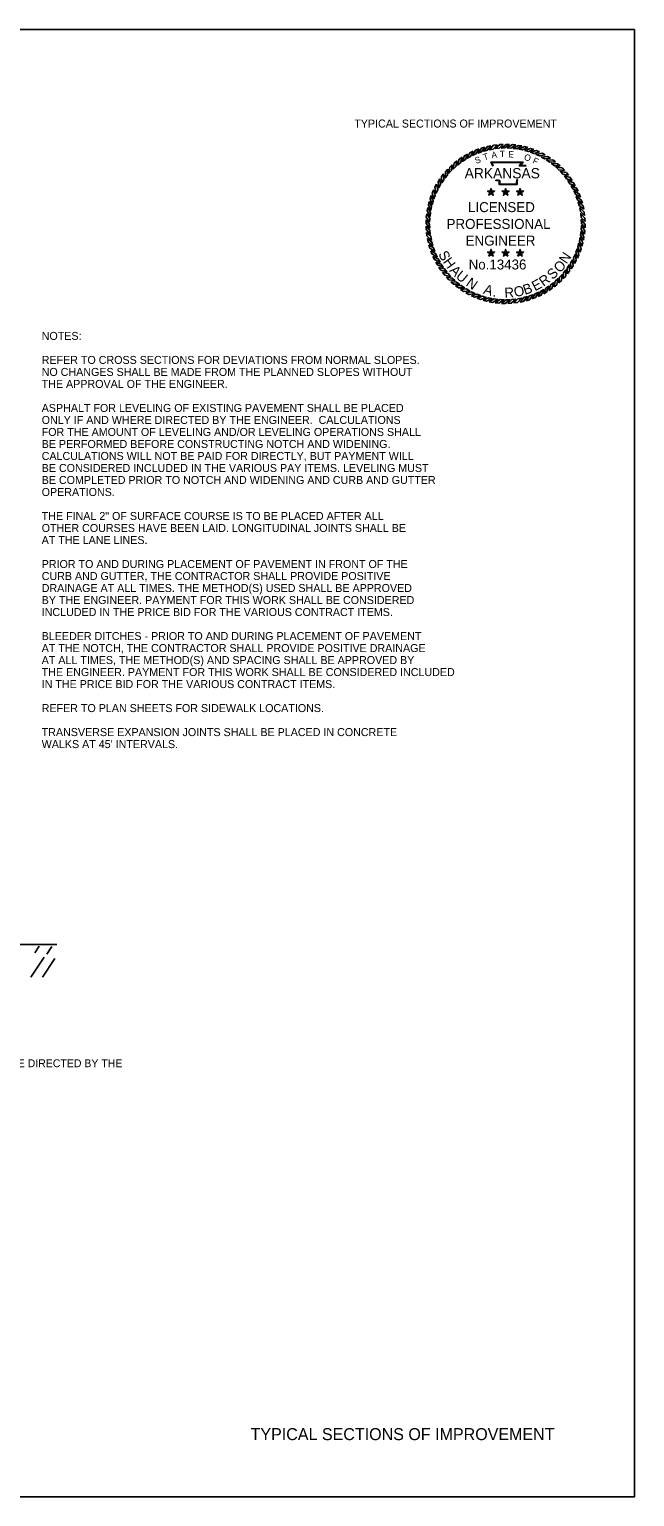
# Model space of a CAD drawing. Extents: x 1001270 to 1003428, y 1840152 to 1842912.
# Drawn here: x 1001928.1 to 1001973.5, y 1840287.7 to 1840397.7 of the extents above; entities that cross this region are included whole.
import ezdxf

# ---------------------------------------------------------------- set-up
doc = ezdxf.new("R2010")
doc.units = 0
for name, color, linetype in [('1', 7, 'Continuous'), ('19', 7, 'Continuous'), ('60', 7, 'Continuous'), ('Default', 7, 'Continuous'), ('G-ANNO-SYMB', 7, 'Continuous')]:
    doc.layers.add(name, color=color, linetype=linetype)

msp = doc.modelspace()

# ---------------------------------------------------------------- linework, layer by layer
at = {"layer": '1'}
msp.add_lwpolyline([(1001973.51, 1840397.72), (1001803.51, 1840397.72), (1001803.51, 1840287.72), (1001973.51, 1840287.72)], close=True, dxfattribs=at)
msp.add_lwpolyline([(1001973.51, 1840397.72), (1001803.51, 1840397.72), (1001803.51, 1840287.72), (1001973.51, 1840287.72)], close=True, dxfattribs=at)
at = {"layer": '19'}
for p, q in [((1001928.51, 1840328.49), (1001928.84, 1840328.98)), ((1001929.41, 1840328.4), (1001929.79, 1840328.97)), ((1001928.22, 1840326.68), (1001929.22, 1840328.16)), ((1001929.08, 1840326.68), (1001930.02, 1840328.06))]:
    msp.add_line(p, q, dxfattribs=at)
msp.add_lwpolyline([(1001877.51, 1840330.24), (1001892.2, 1840330.41), (1001903.17, 1840330.16), (1001908.95, 1840329.52), (1001918.56, 1840329.12), (1001930.17, 1840329.12)], dxfattribs=at)
at = {"layer": 'G-ANNO-SYMB'}
for points in [[(1001963.66, 1840389.1), (1001963.4, 1840389.09), (1001963.06, 1840388.78), (1001963.34, 1840388.81)], [(1001964.12, 1840389.1), (1001963.87, 1840389.1), (1001963.51, 1840388.82), (1001963.78, 1840388.83)], [(1001960.57, 1840388.13), (1001960.35, 1840387.99), (1001960.23, 1840387.55), (1001960.45, 1840387.72)], [(1001960.97, 1840388.37), (1001960.74, 1840388.25), (1001960.58, 1840387.82), (1001960.82, 1840387.97)], [(1001961.39, 1840388.58), (1001961.16, 1840388.47), (1001960.96, 1840388.06), (1001961.2, 1840388.19)], [(1001961.82, 1840388.76), (1001961.58, 1840388.67), (1001961.36, 1840388.27), (1001961.61, 1840388.38)], [(1001962.27, 1840388.9), (1001962.02, 1840388.82), (1001961.77, 1840388.45), (1001962.03, 1840388.54)], [(1001962.73, 1840389), (1001962.47, 1840388.95), (1001962.19, 1840388.59), (1001962.46, 1840388.66)], [(1001963.19, 1840389.07), (1001962.93, 1840389.04), (1001962.62, 1840388.7), (1001962.89, 1840388.75)], [(1001964.59, 1840389.06), (1001964.34, 1840389.08), (1001963.95, 1840388.83), (1001964.23, 1840388.82)], [(1001965.05, 1840388.98), (1001964.8, 1840389.02), (1001964.4, 1840388.8), (1001964.68, 1840388.77)], [(1001965.51, 1840388.86), (1001965.26, 1840388.93), (1001964.84, 1840388.74), (1001965.11, 1840388.68)], [(1001965.95, 1840388.71), (1001965.71, 1840388.8), (1001965.28, 1840388.64), (1001965.55, 1840388.57)], [(1001966.38, 1840388.53), (1001966.15, 1840388.63), (1001965.71, 1840388.51), (1001965.97, 1840388.41)], [(1001966.8, 1840388.31), (1001966.57, 1840388.44), (1001966.12, 1840388.35), (1001966.37, 1840388.23)], [(1001967.19, 1840388.06), (1001966.98, 1840388.2), (1001966.52, 1840388.15), (1001966.77, 1840388.01)], [(1001959.49, 1840387.23), (1001959.32, 1840387.04), (1001959.3, 1840386.59), (1001959.47, 1840386.8)], [(1001959.82, 1840387.56), (1001959.64, 1840387.39), (1001959.58, 1840386.93), (1001959.77, 1840387.13)], [(1001960.18, 1840387.86), (1001959.98, 1840387.7), (1001959.89, 1840387.25), (1001960.1, 1840387.44)], [(1001967.57, 1840387.78), (1001967.37, 1840387.94), (1001966.91, 1840387.92), (1001967.14, 1840387.77)], [(1001967.92, 1840387.48), (1001967.73, 1840387.65), (1001967.28, 1840387.67), (1001967.49, 1840387.49)], [(1001968.25, 1840387.14), (1001968.07, 1840387.33), (1001967.62, 1840387.38), (1001967.82, 1840387.19)], [(1001968.55, 1840386.78), (1001968.39, 1840386.98), (1001967.94, 1840387.07), (1001968.13, 1840386.87)], [(1001958.65, 1840386.11), (1001958.53, 1840385.88), (1001958.62, 1840385.43), (1001958.74, 1840385.69)], [(1001958.9, 1840386.51), (1001958.76, 1840386.29), (1001958.81, 1840385.84), (1001958.95, 1840386.08)], [(1001959.18, 1840386.88), (1001959.02, 1840386.68), (1001959.04, 1840386.22), (1001959.2, 1840386.45)], [(1001968.82, 1840386.4), (1001968.68, 1840386.61), (1001968.24, 1840386.74), (1001968.41, 1840386.52)], [(1001969.06, 1840386), (1001968.93, 1840386.22), (1001968.51, 1840386.38), (1001968.66, 1840386.15)], [(1001969.27, 1840385.58), (1001969.16, 1840385.81), (1001968.75, 1840386), (1001968.88, 1840385.76)], [(1001958.1, 1840384.82), (1001958.04, 1840384.57), (1001958.22, 1840384.16), (1001958.28, 1840384.43)], [(1001958.25, 1840385.26), (1001958.17, 1840385.02), (1001958.32, 1840384.59), (1001958.4, 1840384.86)], [(1001958.44, 1840385.69), (1001958.33, 1840385.46), (1001958.45, 1840385.02), (1001958.55, 1840385.28)], [(1001962.74, 1840385.51), (1001962.67, 1840385.6), (1001962.48, 1840385.6), (1001962.64, 1840385.48)], [(1001962.74, 1840385.51), (1001962.64, 1840385.48), (1001962.58, 1840385.29), (1001962.74, 1840385.41)], [(1001962.74, 1840385.51), (1001962.8, 1840385.6), (1001962.74, 1840385.79), (1001962.67, 1840385.6)], [(1001962.74, 1840385.51), (1001962.83, 1840385.48), (1001963, 1840385.6), (1001962.8, 1840385.6)], [(1001962.74, 1840385.51), (1001962.74, 1840385.41), (1001962.9, 1840385.29), (1001962.83, 1840385.48)], [(1001963.83, 1840385.51), (1001963.77, 1840385.6), (1001963.57, 1840385.6), (1001963.73, 1840385.48)], [(1001963.83, 1840385.51), (1001963.73, 1840385.48), (1001963.67, 1840385.29), (1001963.83, 1840385.41)], [(1001963.83, 1840385.51), (1001963.89, 1840385.6), (1001963.83, 1840385.79), (1001963.77, 1840385.6)], [(1001963.83, 1840385.51), (1001963.93, 1840385.48), (1001964.09, 1840385.6), (1001963.89, 1840385.6)], [(1001963.83, 1840385.51), (1001963.83, 1840385.41), (1001963.99, 1840385.29), (1001963.93, 1840385.48)], [(1001964.92, 1840385.51), (1001964.86, 1840385.6), (1001964.66, 1840385.6), (1001964.82, 1840385.48)], [(1001964.92, 1840385.51), (1001964.82, 1840385.48), (1001964.76, 1840385.29), (1001964.92, 1840385.41)], [(1001964.92, 1840385.51), (1001964.98, 1840385.6), (1001964.92, 1840385.79), (1001964.86, 1840385.6)], [(1001964.92, 1840385.51), (1001965.02, 1840385.48), (1001965.18, 1840385.6), (1001964.98, 1840385.6)], [(1001964.92, 1840385.51), (1001964.92, 1840385.41), (1001965.08, 1840385.29), (1001965.02, 1840385.48)], [(1001969.45, 1840385.14), (1001969.35, 1840385.38), (1001968.96, 1840385.61), (1001969.07, 1840385.36)], [(1001969.59, 1840384.7), (1001969.51, 1840384.94), (1001969.13, 1840385.2), (1001969.23, 1840384.94)], [(1001969.69, 1840384.24), (1001969.64, 1840384.49), (1001969.28, 1840384.78), (1001969.35, 1840384.51)], [(1001957.91, 1840383.9), (1001957.88, 1840383.65), (1001958.13, 1840383.27), (1001958.15, 1840383.54)], [(1001957.99, 1840384.36), (1001957.94, 1840384.11), (1001958.16, 1840383.71), (1001958.2, 1840383.99)], [(1001969.76, 1840383.78), (1001969.73, 1840384.03), (1001969.39, 1840384.34), (1001969.44, 1840384.07)], [(1001969.79, 1840383.31), (1001969.78, 1840383.57), (1001969.47, 1840383.9), (1001969.5, 1840383.63)], [(1001957.87, 1840383.44), (1001957.86, 1840383.18), (1001958.14, 1840382.82), (1001958.13, 1840383.1)], [(1001957.86, 1840382.97), (1001957.88, 1840382.71), (1001958.18, 1840382.37), (1001958.15, 1840382.65)], [(1001957.89, 1840382.5), (1001957.93, 1840382.25), (1001958.26, 1840381.93), (1001958.21, 1840382.21)], [(1001969.67, 1840381.91), (1001969.71, 1840382.16), (1001969.49, 1840382.56), (1001969.46, 1840382.29)], [(1001969.79, 1840382.84), (1001969.79, 1840383.1), (1001969.51, 1840383.46), (1001969.52, 1840383.18)], [(1001969.74, 1840382.37), (1001969.77, 1840382.63), (1001969.52, 1840383.01), (1001969.51, 1840382.73)], [(1001957.96, 1840382.04), (1001958.02, 1840381.79), (1001958.37, 1840381.5), (1001958.3, 1840381.77)], [(1001958.07, 1840381.58), (1001958.14, 1840381.33), (1001958.52, 1840381.08), (1001958.43, 1840381.34)], [(1001969.4, 1840381.01), (1001969.49, 1840381.26), (1001969.33, 1840381.69), (1001969.25, 1840381.42)], [(1001969.55, 1840381.46), (1001969.62, 1840381.71), (1001969.43, 1840382.12), (1001969.37, 1840381.85)], [(1001958.21, 1840381.13), (1001958.3, 1840380.89), (1001958.7, 1840380.67), (1001958.58, 1840380.92)], [(1001958.38, 1840380.7), (1001958.49, 1840380.47), (1001958.91, 1840380.27), (1001958.77, 1840380.52)], [(1001962.74, 1840380.95), (1001962.67, 1840381.03), (1001962.48, 1840381.03), (1001962.64, 1840380.91)], [(1001962.74, 1840380.95), (1001962.64, 1840380.91), (1001962.58, 1840380.73), (1001962.74, 1840380.84)], [(1001962.74, 1840380.95), (1001962.8, 1840381.03), (1001962.74, 1840381.22), (1001962.67, 1840381.03)], [(1001962.74, 1840380.95), (1001962.83, 1840380.91), (1001963, 1840381.03), (1001962.8, 1840381.03)], [(1001962.74, 1840380.95), (1001962.74, 1840380.84), (1001962.9, 1840380.73), (1001962.83, 1840380.91)], [(1001963.83, 1840380.95), (1001963.77, 1840381.03), (1001963.57, 1840381.03), (1001963.73, 1840380.91)], [(1001963.83, 1840380.95), (1001963.73, 1840380.91), (1001963.67, 1840380.73), (1001963.83, 1840380.84)], [(1001963.83, 1840380.95), (1001963.89, 1840381.03), (1001963.83, 1840381.22), (1001963.77, 1840381.03)], [(1001963.83, 1840380.95), (1001963.93, 1840380.91), (1001964.09, 1840381.03), (1001963.89, 1840381.03)], [(1001963.83, 1840380.95), (1001963.83, 1840380.84), (1001963.99, 1840380.73), (1001963.93, 1840380.91)], [(1001964.92, 1840380.95), (1001964.86, 1840381.03), (1001964.66, 1840381.03), (1001964.82, 1840380.91)], [(1001964.92, 1840380.95), (1001964.82, 1840380.91), (1001964.76, 1840380.73), (1001964.92, 1840380.84)], [(1001964.92, 1840380.95), (1001964.98, 1840381.03), (1001964.92, 1840381.22), (1001964.86, 1840381.03)], [(1001964.92, 1840380.95), (1001965.02, 1840380.91), (1001965.18, 1840381.03), (1001964.98, 1840381.03)], [(1001964.92, 1840380.95), (1001964.92, 1840380.84), (1001965.08, 1840380.73), (1001965.02, 1840380.91)], [(1001968.75, 1840379.77), (1001968.89, 1840379.99), (1001968.84, 1840380.44), (1001968.7, 1840380.2)], [(1001969, 1840380.17), (1001969.12, 1840380.39), (1001969.04, 1840380.84), (1001968.92, 1840380.59)], [(1001969.22, 1840380.58), (1001969.32, 1840380.82), (1001969.2, 1840381.26), (1001969.1, 1840381)], [(1001958.59, 1840380.28), (1001958.72, 1840380.06), (1001959.15, 1840379.9), (1001958.99, 1840380.13)], [(1001958.83, 1840379.88), (1001958.98, 1840379.67), (1001959.42, 1840379.54), (1001959.25, 1840379.76)], [(1001959.1, 1840379.5), (1001959.26, 1840379.3), (1001959.71, 1840379.2), (1001959.52, 1840379.41)], [(1001967.83, 1840378.71), (1001968.02, 1840378.89), (1001968.07, 1840379.34), (1001967.88, 1840379.14)], [(1001968.16, 1840379.04), (1001968.34, 1840379.23), (1001968.36, 1840379.69), (1001968.18, 1840379.47)], [(1001968.47, 1840379.4), (1001968.63, 1840379.6), (1001968.61, 1840380.06), (1001968.46, 1840379.83)], [(1001959.4, 1840379.14), (1001959.58, 1840378.95), (1001960.03, 1840378.89), (1001959.83, 1840379.08)], [(1001959.73, 1840378.8), (1001959.92, 1840378.63), (1001960.38, 1840378.61), (1001960.16, 1840378.78)], [(1001960.08, 1840378.49), (1001960.29, 1840378.34), (1001960.74, 1840378.35), (1001960.51, 1840378.51)], [(1001960.46, 1840378.21), (1001960.67, 1840378.07), (1001961.13, 1840378.13), (1001960.89, 1840378.26)], [(1001966.27, 1840377.69), (1001966.5, 1840377.8), (1001966.69, 1840378.22), (1001966.45, 1840378.08)], [(1001966.69, 1840377.9), (1001966.91, 1840378.03), (1001967.07, 1840378.46), (1001966.84, 1840378.31)], [(1001967.09, 1840378.14), (1001967.3, 1840378.29), (1001967.43, 1840378.73), (1001967.21, 1840378.56)], [(1001967.47, 1840378.41), (1001967.67, 1840378.57), (1001967.76, 1840379.02), (1001967.56, 1840378.84)], [(1001960.86, 1840377.96), (1001961.08, 1840377.84), (1001961.53, 1840377.93), (1001961.28, 1840378.05)], [(1001961.27, 1840377.75), (1001961.51, 1840377.64), (1001961.95, 1840377.76), (1001961.69, 1840377.86)], [(1001961.7, 1840377.56), (1001961.94, 1840377.48), (1001962.37, 1840377.63), (1001962.11, 1840377.71)], [(1001962.15, 1840377.41), (1001962.39, 1840377.35), (1001962.81, 1840377.54), (1001962.54, 1840377.59)], [(1001962.6, 1840377.3), (1001962.85, 1840377.25), (1001963.25, 1840377.47), (1001962.98, 1840377.51)], [(1001963.06, 1840377.22), (1001963.32, 1840377.19), (1001963.7, 1840377.45), (1001963.42, 1840377.46)], [(1001963.53, 1840377.18), (1001963.79, 1840377.17), (1001964.15, 1840377.45), (1001963.87, 1840377.45)], [(1001964, 1840377.17), (1001964.25, 1840377.19), (1001964.59, 1840377.5), (1001964.31, 1840377.47)], [(1001964.46, 1840377.21), (1001964.72, 1840377.24), (1001965.03, 1840377.57), (1001964.76, 1840377.52)], [(1001964.93, 1840377.27), (1001965.18, 1840377.33), (1001965.46, 1840377.69), (1001965.2, 1840377.61)], [(1001965.38, 1840377.38), (1001965.63, 1840377.45), (1001965.89, 1840377.83), (1001965.63, 1840377.74)], [(1001965.83, 1840377.52), (1001966.07, 1840377.61), (1001966.3, 1840378.01), (1001966.04, 1840377.89)]]:
    msp.add_lwpolyline(points, close=True, dxfattribs=at)
for points in [[(1001962.87, 1840387.47), (1001962.73, 1840387.77), (1001965.14, 1840387.77), (1001964.94, 1840387.52), (1001965.1, 1840387.52), (1001965.24, 1840387.52), (1001965.37, 1840387.51)], [(1001962.91, 1840387.48), (1001962.79, 1840387.73), (1001965.06, 1840387.73), (1001964.86, 1840387.48), (1001965.1, 1840387.48), (1001965.24, 1840387.48), (1001965.37, 1840387.47)], [(1001964.76, 1840386.46), (1001964.72, 1840386.43), (1001964.7, 1840386.38), (1001964.69, 1840386.25), (1001964.69, 1840386.09), (1001963.35, 1840386.09), (1001963.35, 1840386.31), (1001963.35, 1840386.36), (1001963.29, 1840386.38), (1001963.1, 1840386.38), (1001963.07, 1840386.43)], [(1001964.73, 1840386.49), (1001964.68, 1840386.45), (1001964.67, 1840386.38), (1001964.65, 1840386.25), (1001964.65, 1840386.12), (1001963.39, 1840386.12), (1001963.39, 1840386.31), (1001963.39, 1840386.39), (1001963.3, 1840386.41), (1001963.12, 1840386.41), (1001963.1, 1840386.45)]]:
    msp.add_lwpolyline(points, dxfattribs=at)

# ---------------------------------------------------------------- texts
at = {"layer": '1'}
msp.add_text('TYPICAL SECTIONS OF IMPROVEMENT', height=0.6, dxfattribs=at).set_placement((1001952.48, 1840390.36))
at = {"layer": '19'}
for s, p in [('NOTES:', (1001929.03, 1840374.44)), ('REFER TO CROSS SECTIONS FOR DEVIATIONS FROM NORMAL SLOPES.', (1001929.03, 1840372.64)), ('NO CHANGES SHALL BE MADE FROM THE PLANNED SLOPES WITHOUT', (1001929.03, 1840371.74)), ('THE APPROVAL OF THE ENGINEER.', (1001929.03, 1840370.84)), ('ASPHALT FOR LEVELING OF EXISTING PAVEMENT SHALL BE PLACED', (1001929.03, 1840369.04)), ('ONLY IF AND WHERE DIRECTED BY THE ENGINEER.  CALCULATIONS', (1001929.03, 1840368.14)), ('FOR THE AMOUNT OF LEVELING AND/OR LEVELING OPERATIONS SHALL', (1001929.03, 1840367.24)), ('CALCULATIONS WILL NOT BE PAID FOR DIRECTLY, BUT PAYMENT WILL', (1001929.03, 1840365.44)), ('BE PERFORMED BEFORE CONSTRUCTING NOTCH AND WIDENING.', (1001929.03, 1840366.34)), ('BE CONSIDERED INCLUDED IN THE VARIOUS PAY ITEMS. LEVELING MUST ', (1001929.03, 1840364.54)), ('BE COMPLETED PRIOR TO NOTCH AND WIDENING AND CURB AND GUTTER', (1001929.03, 1840363.64)), ('OPERATIONS. ', (1001929.03, 1840362.74)), ('THE FINAL 2" OF SURFACE COURSE IS TO BE PLACED AFTER ALL', (1001929.03, 1840360.94)), ('OTHER COURSES HAVE BEEN LAID. LONGITUDINAL JOINTS SHALL BE', (1001929.03, 1840360.04)), ('AT THE LANE LINES.', (1001929.03, 1840359.14)), ('PRIOR TO AND DURING PLACEMENT OF PAVEMENT IN FRONT OF THE', (1001929.03, 1840357.34)), ('CURB AND GUTTER, THE CONTRACTOR SHALL PROVIDE POSITIVE', (1001929.03, 1840356.44)), ('DRAINAGE AT ALL TIMES. THE METHOD(S) USED SHALL BE APPROVED', (1001929.03, 1840355.54)), ('BY THE ENGINEER. PAYMENT FOR THIS WORK SHALL BE CONSIDERED', (1001929.03, 1840354.64)), ('INCLUDED IN THE PRICE BID FOR THE VARIOUS CONTRACT ITEMS.', (1001929.03, 1840353.74)), ('BLEEDER DITCHES - PRIOR TO AND DURING PLACEMENT OF PAVEMENT', (1001929.03, 1840351.94)), ('AT THE NOTCH, THE CONTRACTOR SHALL PROVIDE POSITIVE DRAINAGE', (1001929.03, 1840351.04)), ('AT ALL TIMES, THE METHOD(S) AND SPACING SHALL BE APPROVED BY', (1001929.03, 1840350.14)), ('THE ENGINEER. PAYMENT FOR THIS WORK SHALL BE CONSIDERED INCLUDED', (1001929.03, 1840349.24)), ('IN THE PRICE BID FOR THE VARIOUS CONTRACT ITEMS.', (1001929.03, 1840348.34)), ('REFER TO PLAN SHEETS FOR SIDEWALK LOCATIONS.', (1001929.03, 1840346.54)), ('TRANSVERSE EXPANSION JOINTS SHALL BE PLACED IN CONCRETE', (1001929.03, 1840344.74)), ("WALKS AT 45' INTERVALS.", (1001929.03, 1840343.84))]:
    msp.add_text(s, height=0.6, dxfattribs=at).set_placement(p)
at = {"layer": '60'}
msp.add_text('TYPICAL SECTIONS OF IMPROVEMENT', height=0.9, dxfattribs=at).set_placement((1001944.7, 1840291.96))
at = {"layer": 'Default'}
msp.add_text('TO BE USED IF AND WHERE DIRECTED BY THE ', height=0.59, rotation=359.9954, dxfattribs=at).set_placement((1001917.02, 1840319.92))
at = {"layer": 'G-ANNO-SYMB'}
for s, height, rotation, p in [('S', 0.475, 19.7726, (1001961.62, 1840387.63)), ('T', 0.475, 16.9015, (1001962.22, 1840387.9)), ('A', 0.475, 8.6788, (1001962.8, 1840388.05)), ('T', 0.475, 1.4789, (1001963.41, 1840388.14)), ('E', 0.475, 356.672, (1001964.02, 1840388.13)), ('O', 0.475, 341.2218, (1001965.17, 1840387.96)), ('F', 0.475, 335.3628, (1001965.81, 1840387.71)), ('ARKANSAS', 0.775, 360, (1001960.76, 1840386.55)), ('LICENSED', 0.75, 360, (1001961.01, 1840384.02)), ('PROFESSIONAL', 0.75, 360, (1001959.4, 1840382.76)), ('ENGINEER', 0.75, 360, (1001960.83, 1840381.51)), ('S', 0.75, 298.1636, (1001958.76, 1840380.88)), ('H', 0.75, 305.619, (1001959.1, 1840380.29)), ('No.13436', 0.747, 360, (1001961.06, 1840379.72)), ('O', 0.75, 44.7757, (1001967.88, 1840379.42)), ('N', 0.75, 56.1007, (1001968.4, 1840380.09)), ('A', 0.75, 313.4472, (1001959.58, 1840379.61)), ('U', 0.75, 320.9026, (1001960.04, 1840379.12)), ('R', 0.75, 35.6597, (1001966.67, 1840378.41)), ('S', 0.75, 43.4878, (1001967.36, 1840378.92)), ('N', 0.75, 324.9326, (1001960.8, 1840378.56)), ('A', 0.75, 343.0991, (1001962.11, 1840377.92)), ('R', 0.75, 3.2287, (1001963.76, 1840377.6)), ('O', 0.75, 11.4296, (1001964.53, 1840377.65)), ('B', 0.75, 18.885, (1001965.28, 1840377.81)), ('E', 0.75, 27.8315, (1001966.04, 1840378.08)), ('.', 0.75, 351.3, (1001962.84, 1840377.7))]:
    msp.add_text(s, height=height, rotation=rotation, dxfattribs=at).set_placement(p)

doc.saveas('drawing.dxf')
